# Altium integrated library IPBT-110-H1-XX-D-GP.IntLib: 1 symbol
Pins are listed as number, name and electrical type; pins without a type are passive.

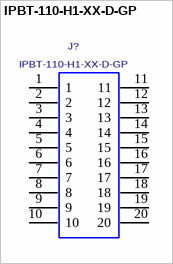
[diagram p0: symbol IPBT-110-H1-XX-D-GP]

## IPBT-110-H1-XX-D-GP
designator J?
Power-Mate Header, Double Row, 0.165" Pitch; MANUFACTURER: SAMTEC
footprint IPBT-110-H1-XX-D-GP
pins: 1, 2, 3, 4, 5, 6, 7, 8, 9, 10, 11, 12, 13, 14, 15, 16, 17, 18, 19, 20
